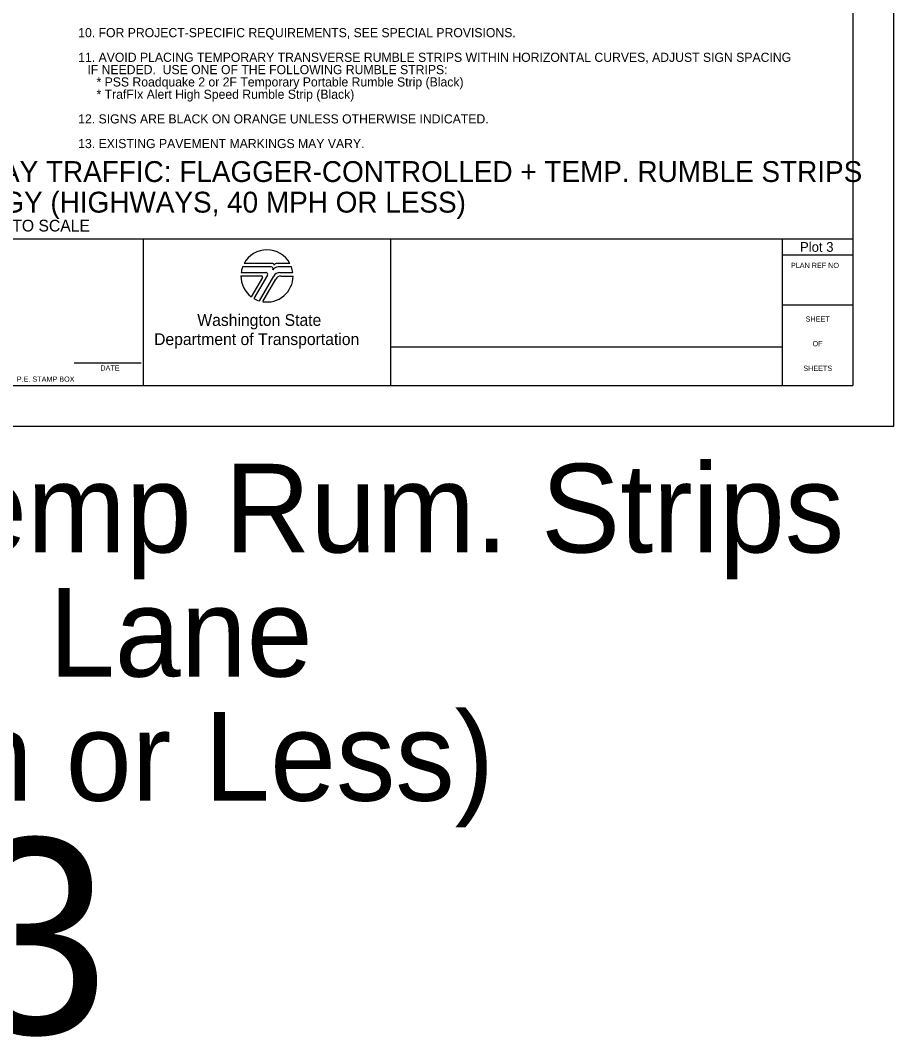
# Model space of a CAD drawing. Extents: x 99998.9 to 100095.7, y 99995 to 100010.7.
# Drawn here: x 100049.37 to 100056.06, y 99995.01 to 100002.8 of the extents above; entities that cross this region are included whole.
import ezdxf

# ---------------------------------------------------------------- set-up
doc = ezdxf.new("R2010")
doc.units = 0
for name, color, linetype in [('SH_DE_DetailHeading1Text', 7, 'Continuous'), ('SH_GI_GeneralNotesBodyText', 7, 'Continuous'), ('SH_GI_PlotLimits', 7, 'Continuous'), ('SH_GI_SheetBorder', 7, 'Continuous'), ('SH_GI_SheetLocationText', 7, 'Continuous'), ('SH_GI_SheetTextInCells', 7, 'Continuous'), ('SH_GI_WSDOTLogo', 7, 'Continuous')]:
    doc.layers.add(name, color=color, linetype=linetype)

msp = doc.modelspace()

# ---------------------------------------------------------------- linework, layer by layer
at = {"layer": 'SH_GI_PlotLimits'}
msp.add_lwpolyline([(100039.0625, 99999.6875), (100056.0625, 99999.6875), (100056.0625, 100010.6875), (100039.0625, 100010.6875)], close=True, dxfattribs=at)
at = {"layer": 'SH_GI_SheetBorder'}
for p, q in [((100055.75, 100010.375), (100055.75, 100000)), ((100040, 100001.1259), (100055.75, 100001.1259)), ((100050.3089, 100001.1259), (100050.3089, 100000)), ((100052.2055, 100001.1259), (100052.2055, 100000)), ((100055.2079, 100001.1259), (100055.2079, 100000)), ((100055.2079, 100001.0008), (100055.75, 100001.0008)), ((100055.2079, 100000.6176), (100055.75, 100000.6176)), ((100052.2055, 100000.2955), (100055.2079, 100000.2955)), ((100049.7797, 100000.1733), (100050.2914, 100000.1733)), ((100040, 100000), (100055.75, 100000))]:
    msp.add_line(p, q, dxfattribs=at)
at = {"layer": 'SH_GI_WSDOTLogo'}
for p, q in [((100051.2894, 100000.9094), (100051.0697, 100000.9094)), ((100051.303, 100000.9354), (100051.0815, 100000.9354)), ((100051.433, 100000.9354), (100051.3351, 100000.9354)), ((100051.343, 100000.9094), (100051.3429, 100000.9094)), ((100051.4448, 100000.9094), (100051.343, 100000.9094)), ((100051.0572, 100000.84), (100051.2148, 100000.84)), ((100051.059, 100000.8661), (100051.2496, 100000.8661)), ((100051.222, 100000.8277), (100051.1364, 100000.6807)), ((100051.261, 100000.8464), (100051.1567, 100000.6672)), ((100051.1989, 100000.6487), (100051.3089, 100000.839)), ((100051.3558, 100000.8661), (100051.4555, 100000.8661)), ((100051.3655, 100000.8394), (100051.4572, 100000.8394)), ((100051.2244, 100000.6428), (100051.3242, 100000.8156))]:
    msp.add_line(p, q, dxfattribs=at)
for centre, radius, start, end in [((100051.2572, 100000.84), 0.2, 28.47865, 151.53204), ((100051.2572, 100000.84), 0.2, 159.69598, 172.50569), ((100051.2894, 100000.8946), 0.0148, 327.8418, 89.99855), ((100051.3429, 100000.861), 0.0484, 89.99529, 147.82376), ((100051.303, 100000.9263), 0.00903, 329.87418, 90.00328), ((100051.3352, 100000.9066), 0.0287, 90.00721, 148.16763), ((100051.2572, 100000.84), 0.2, 7.49431, 20.29406), ((100051.2572, 100000.84), 0.2, 179.99864, 232.84327), ((100051.2149, 100000.8318), 0.0082, 329.74356, 90), ((100051.2572, 100000.84), 0.2, 260.54554, 359.80857), ((100051.2497, 100000.853), 0.0131, 329.76834, 90), ((100051.3558, 100000.8119), 0.0542, 90, 149.99738), ((100051.3654, 100000.7918), 0.0476, 90, 150.05432), ((100051.2572, 100000.84), 0.2, 239.79292, 253.0448)]:
    msp.add_arc(centre, radius, start, end, dxfattribs=at)

# ---------------------------------------------------------------- texts
at = {"layer": 'SH_DE_DetailHeading1Text'}
for s, height, p in [('PILOT CAR OPERATION FOR ALTERNATING 1-LANE, 2-WAY TRAFFIC: FLAGGER-CONTROLLED + TEMP. RUMBLE STRIPS', 0.16, (100043.3806, 100001.5606)), ('SEPARATED BICYCLE LANE STRATEGY (HIGHWAYS, 40 MPH OR LESS)', 0.16, (100045.435, 100001.3259)), ('NOT TO SCALE', 0.09, (100049.0168, 100001.1809))]:
    msp.add_text(s, height=height, rotation=360, dxfattribs=at).set_placement(p)
at = {"layer": 'SH_GI_GeneralNotesBodyText'}
for s, p in [('10. FOR PROJECT-SPECIFIC REQUIREMENTS, SEE SPECIAL PROVISIONS.', (100049.8098, 100002.6711)), ('11. AVOID PLACING TEMPORARY TRANSVERSE RUMBLE STRIPS WITHIN HORIZONTAL CURVES, ADJUST SIGN SPACING ', (100049.8098, 100002.4821)), ('IF NEEDED.  USE ONE OF THE FOLLOWING RUMBLE STRIPS:', (100049.88, 100002.3876)), ('* PSS Roadquake 2 or 2F Temporary Portable Rumble Strip (Black)', (100049.9498, 100002.2931)), ('* TrafFIx Alert High Speed Rumble Strip (Black)', (100049.9498, 100002.1986)), ('12. SIGNS ARE BLACK ON ORANGE UNLESS OTHERWISE INDICATED.', (100049.8098, 100002.0096)), ('13. EXISTING PAVEMENT MARKINGS MAY VARY.', (100049.8098, 100001.8206))]:
    msp.add_text(s, height=0.07, rotation=360, dxfattribs=at).set_placement(p)
at = {"layer": 'SH_GI_SheetBorder'}
msp.add_text('PLAN REF NO', height=0.040032, dxfattribs=at).set_placement((100055.2747, 100000.9008))
at = {"layer": 'SH_GI_SheetLocationText'}
for s, height, p in [('Plot 3', 0.075, (100055.3446, 100001.025)), ('Pilot Car Op: Flagger + Temp Rum. Strips', 0.68, (100038.7792, 99998.7191)), ('Separated Bike Lane', 0.68, (100043.1141, 99997.7671)), ('(Highways, 40 mph or Less)', 0.68, (100041.6785, 99996.8151)), ('Plot 3', 1.5, (100044.9133, 99995.0267))]:
    msp.add_text(s, height=height, dxfattribs=at).set_placement(p)
at = {"layer": 'SH_GI_SheetTextInCells'}
for s, height, p in [('Washington State', 0.090072, (100050.7229, 100000.4571)), ('SHEET', 0.04003, (100055.3877, 100000.4896)), ('Department of Transportation', 0.090072, (100050.3916, 100000.3101)), ('OF', 0.04003, (100055.4406, 100000.3008)), ('DATE', 0.04003, (100049.9794, 100000.1141)), ('SHEETS', 0.04003, (100055.3698, 100000.112)), ('P.E. STAMP BOX', 0.040032, (100049.339, 100000.0286))]:
    msp.add_text(s, height=height, dxfattribs=at).set_placement(p)

doc.saveas('drawing.dxf')
